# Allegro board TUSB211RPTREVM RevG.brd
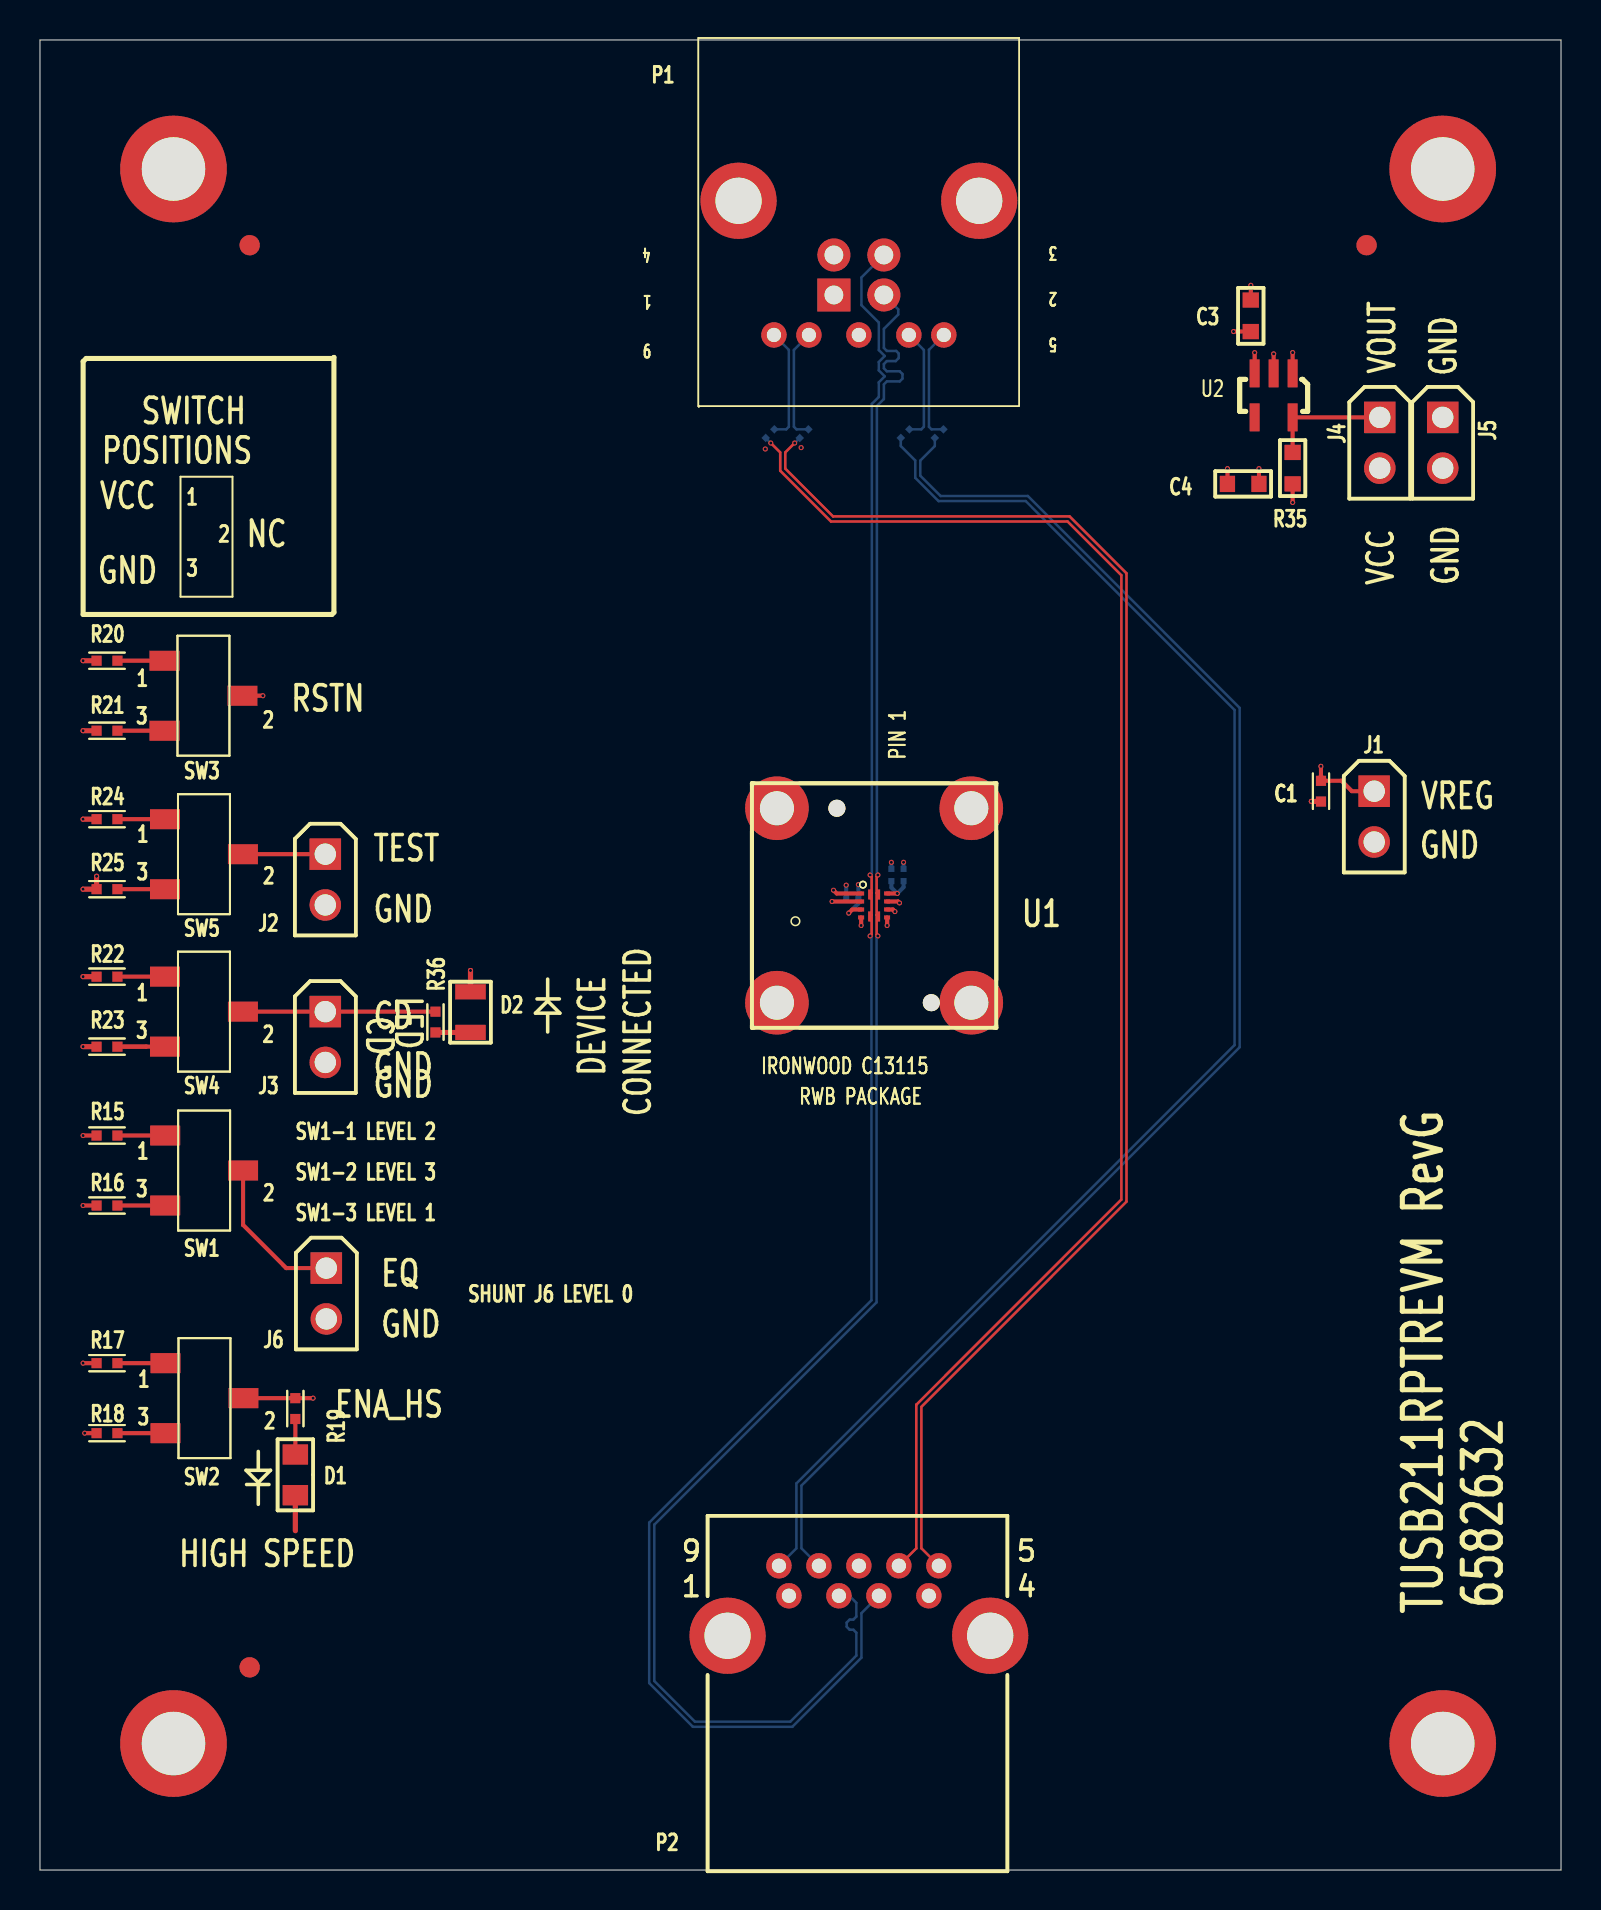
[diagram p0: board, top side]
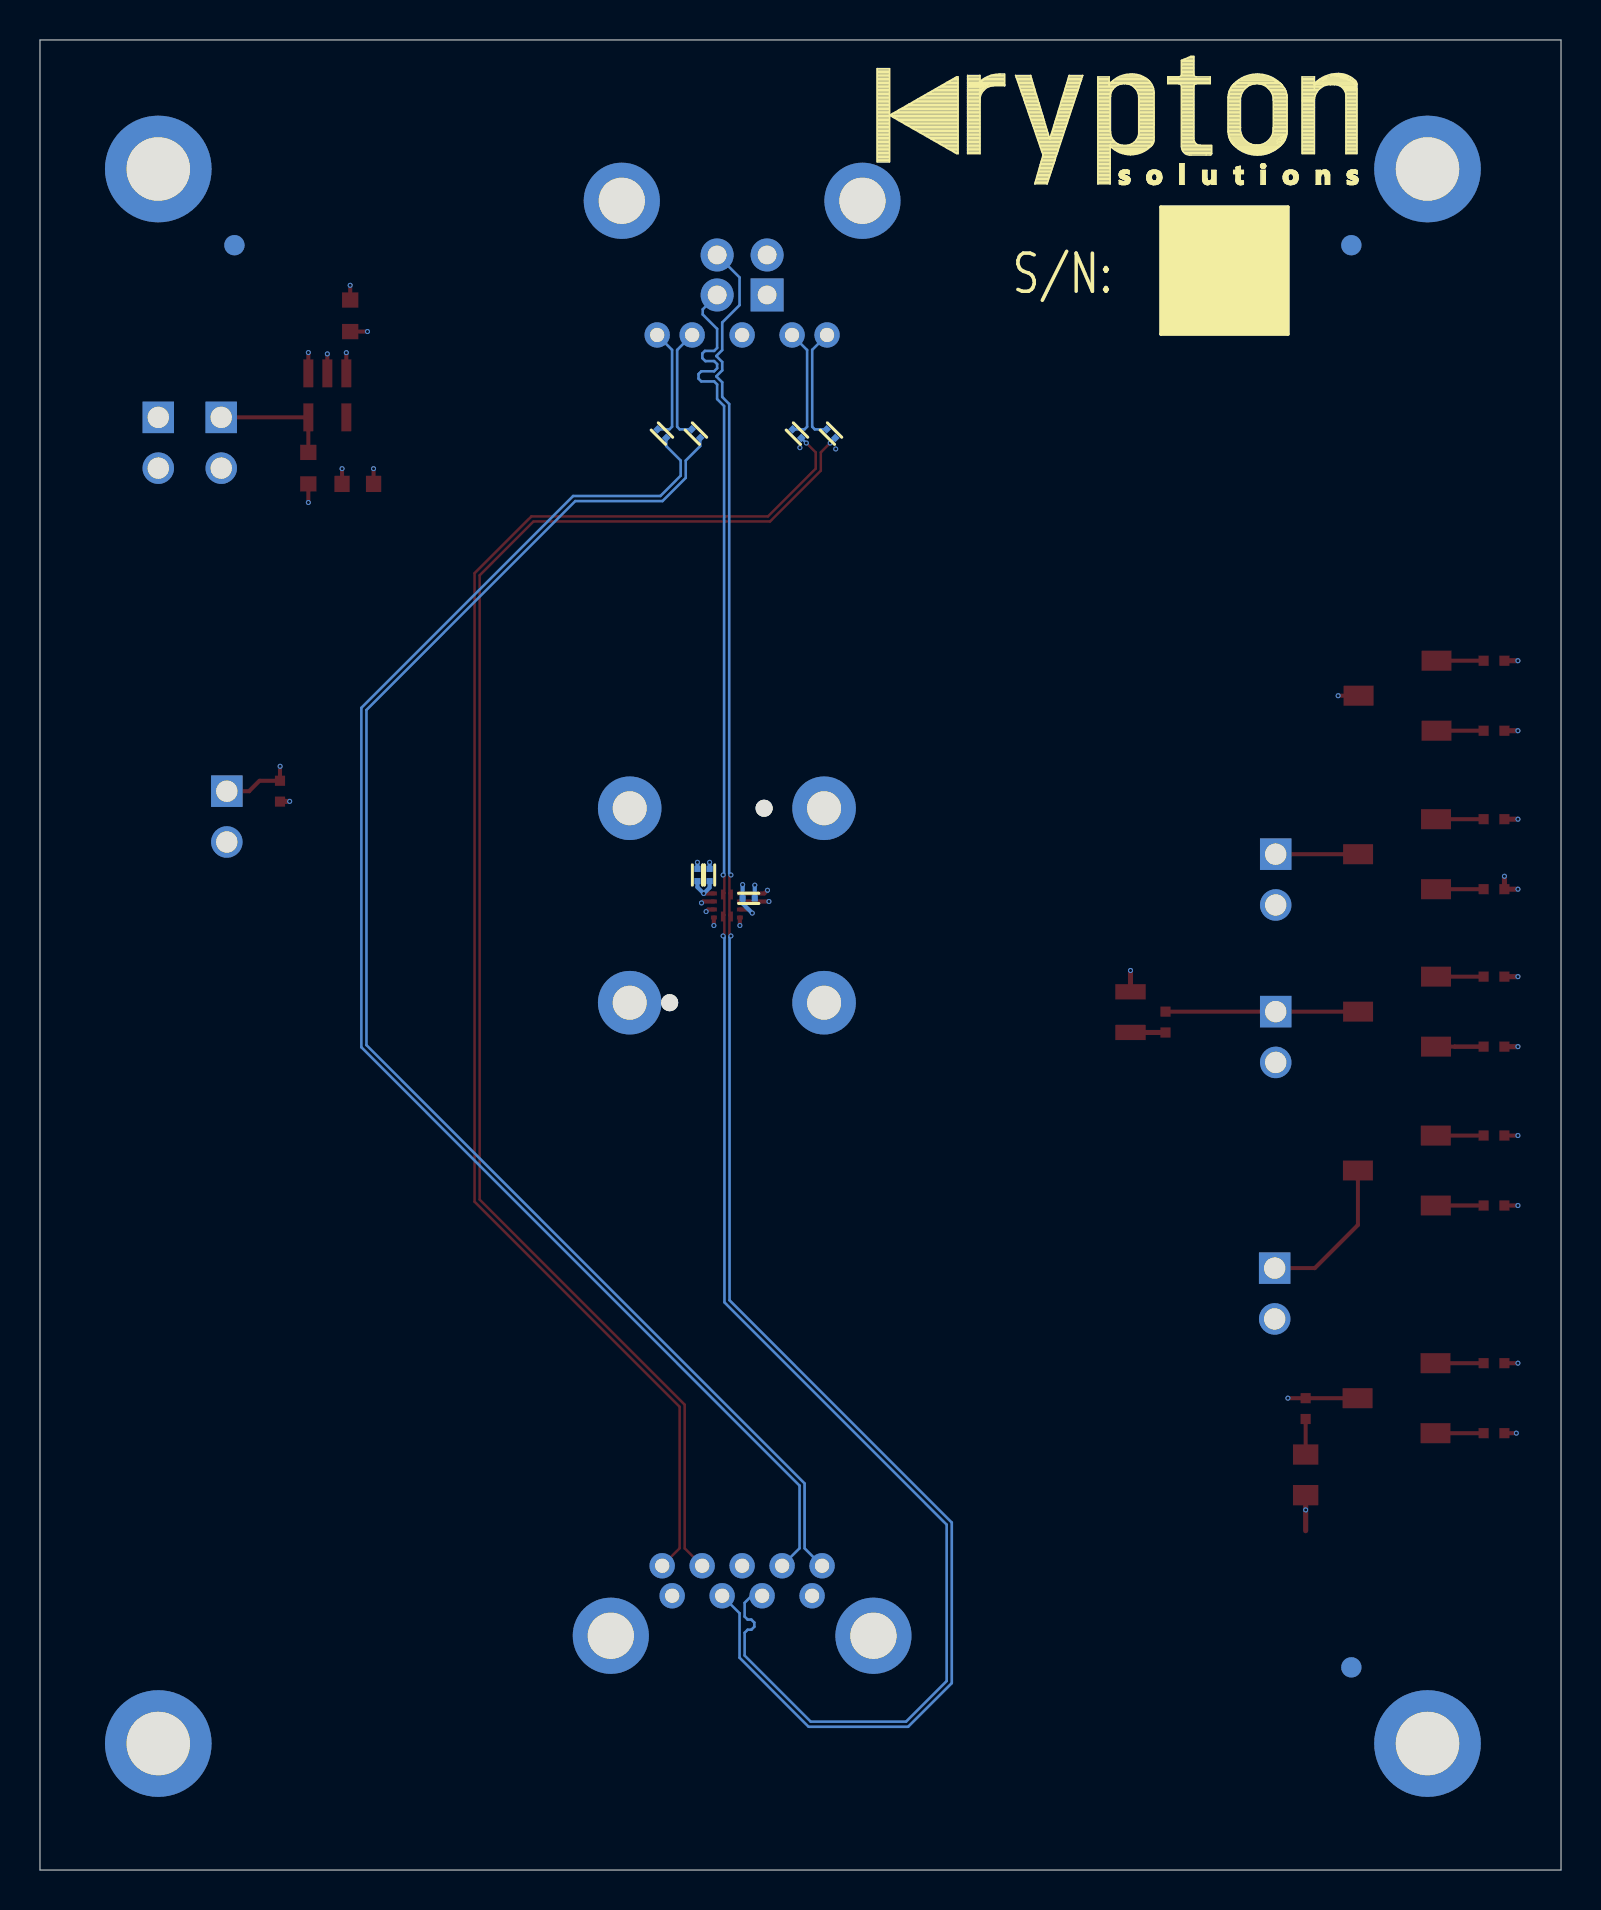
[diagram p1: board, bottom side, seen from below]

Outline 76.1 x 91.52 mm; copper layers: TOP, L2, L3, L4, L5, BOTTOM. Coordinates in mm from the lower left corner of the outline.
Outline path: 0,91.52 76.1,91.52 76.1,0 0,0 0,91.52

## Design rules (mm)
constraint set DEFAULT: min track width 0.127
net group DIFFPAIR4: nets SS_P2_RXN SS_P2_RXP
net group DIFFPAIR5: nets SS_P2_TXN SS_P2_TXP
net group DP1: nets N16594201 N16594205

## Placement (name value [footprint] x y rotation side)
C1  0.1uF  [0402]  64.09 53.95 270 top
C2  0.1uF  [0201]  40.64 48.59 180 bottom
C3  1uF  [0603]  60.58 77.72 90 top
C4  1uF  [0603]  60.2 69.32 180 top
C5  1uF  [0201]  42.6 49.76 90 bottom
C6  0.1uF  [0201]  43.21 49.76 90 bottom
D1  LED  [0805]  12.78 19.76 90 top
D2  LED  [CC0805]  21.54 43.92 270 top
J1  HDR2X1 M .1  [CON_THVT_1X2_100_M]  66.75 53.95 180 top
J2  HDR2X1 M .1  [CON_THVT_1X2_100_M]  14.27 50.8 180 top
J3  HDR2X1 M .1  [CON_THVT_1X2_100_M]  14.27 42.93 180 top
J4  HDR2X1 M .1  [CON_THVT_1X2_100_M]  67.03 72.64 180 top
J5  HDR2X1 M .1  [CON_THVT_1X2_100_M]  70.18 72.64 180 top
J6  HDR2X1 M .1  [CON_THVT_1X2_100_M]  14.33 30.1 180 top
M*  -  [unnamed]  6.68 85.06 0 top
M*#2  -  [unnamed]  70.18 6.32 0 top
M*#3  -  [unnamed]  70.18 85.06 0 top
M*#4  -  [unnamed]  6.68 6.32 0 top
NOREF  -  [#2]  847.93 330.56 0 top
NOREF#2  -  [#2]  76.1 0 90 top
NOREF#3  -  [unnamed]  10.49 10.13 0 top
NOREF#4  -  [#2]  -0.46 -18.57 0 top
NOREF#5  -  [#2]  96.6 85.95 0 top
NOREF#6  -  [unnamed]  10.49 81.25 0 top
NOREF#7  -  [unnamed]  66.37 81.25 0 top
NOREF#8  -  [#2]  66.95 3.91 90 top
NOREF#9  -  [#2]  0 91.52 0 top
NOREF#10  -  [unnamed]  66.37 81.25 180 bottom
NOREF#11  -  [unnamed]  10.49 81.25 180 bottom
NOREF#12  -  [#2]  22.2 8.08 180 bottom
NOREF#13  -  [#2]  27 79.98 180 bottom
NOREF#14  -  [#2]  34.26 84.25 180 bottom
NOREF#15  -  [unnamed]  10.49 10.13 180 bottom
P1  USB3_STANDARD_TYPE_B_RECEPTACLE  [USB3_TYPEB_AK4AA009]  39.72 78.77 180 top
P2  USB3_STANDARD_TYPE-A_RECEPTACLE  [USB3_TYPEA]  40.97 15.21 0 top
R3  0 Ohm  [0201]  44.98 71.83 225 bottom
R4  0 Ohm  [0201]  43.28 71.83 225 bottom
R5  0 Ohm  [0201]  38.23 71.83 225 bottom
R6  0 Ohm  [0201]  36.53 71.83 225 bottom
R15  4k Ohm  [0402]  3.35 36.73 0 top
R16  2k Ohm  [0402]  3.35 33.23 180 top
R17  4.7k  [0402]  3.35 25.35 0 top
R18  0 Ohm  [0402]  3.35 21.85 0 top
R19  75  [0402]  12.78 23.08 270 top
R20  4.7k  [0402]  3.35 60.47 0 top
R21  0 Ohm  [0402]  3.35 56.97 180 top
R22  4.7k  [0402]  3.35 44.68 0 top
R23  0 Ohm  [0402]  3.35 41.18 180 top
R24  4.7k  [0402]  3.35 52.55 0 top
R25  0 Ohm  [0402]  3.35 49.05 180 top
R35  0 Ohm  [0603]  62.67 70.1 270 top
R36  75  [0402]  19.79 42.41 270 top
SW1  Switch CJS-1201  [CJS-1200B]  8.21 34.98 0 top
SW2  Switch CJS-1201  [CJS-1200B]  8.23 23.6 0 top
SW3  Switch CJS-1201  [CJS-1200B]  8.18 58.72 0 top
SW4  Switch CJS-1201  [CJS-1200B]  8.2 42.93 0 top
SW5  Switch CJS-1201  [CJS-1200B]  8.2 50.8 0 top
U1  TUSB2x1RWB  [IRONWOOD_12PIN_C13115]  41.73 48.23 270 top
U2  LP5907  [DBV_R-PDSO-G5]  61.72 73.74 270 top

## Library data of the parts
C1 C2 C6 = cc0402
C3-C5 = cc0603
D1 = d0805 Green
D2 = d0805 Yellow
J1-J6 = HDR2X1 M .1
P1 = USB3_STANDARD_TYPE_B_RECEPTACLE
P2 = USB3_STANDARD_TYPE-A_RECEPTACLE
R3-R6 = r0201
R15-R25 R36 = r0402
R35 = r0603
SW1-SW5 = Switch CJS-1201
U1 = TUSB2x1RWB_0
U2 = LP5907

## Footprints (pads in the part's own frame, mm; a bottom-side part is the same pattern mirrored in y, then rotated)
0201
  rect 0.305x0.305 smd: 1(-0.305,0) 2(0.305,0)
0402
  rect 0.508x0.508 smd: 1(-0.521,0) 2(0.521,0)
0603
  rect 0.762x0.813 smd: 1(-0.787,0) 2(0.787,0)
0805
  rect 1.016x1.27 smd: 1(-1.016,0) 2(1.016,0)
CC0805
  rect 0.762x1.524 smd: 1(0,0) 2(2.032,0)
CJS-1200B
  rect 1.5x1 smd: 1(-1.95,1.75) 2(1.95,0) 3(-1.95,-1.75)
CON_THVT_1X2_100_M
  rect 1.575x1.575 hole 1.067: 1(0,0)
  round 1.575 hole 1.067: 2(0,2.54)
DBV_R-PDSO-G5
  rect 1.4x0.5 smd: 1(-1.1,0.95) 2(-1.1,0) 3(-1.1,-0.95) 4(1.1,-0.95) 5(1.1,0.95)
IRONWOOD_12PIN_C13115
  round 3.18 hole 1.7: (-4.862,4.862) (-4.862,-4.862) (4.862,4.862) (4.862,-4.862)
  round 0.85 hole 0.85 unplated: (-4.862,-1.862) (4.862,2.862)
  rect 0.5x0.2 smd: 1(-0.55,0.2) 2(-0.55,-0.2) 7(0.55,-0.2) 8(0.55,0.2)
  rect 0.2x0.3 smd: 3(-0.6,-0.65) 4(-0.2,-0.65) 5(0.2,-0.65) 6(0.6,-0.65) 9(0.6,0.65) 10(0.2,0.65) 11(-0.2,0.65) 12(-0.6,0.65)
unnamed
  round 5.334 hole 3.175: (0,0)
USB3_TYPEA
  round 1.27 hole 0.711: 1(-3.5,-1.5) 2(-1,-1.5) 3(1,-1.5) 4(3.5,-1.5) 5(4,0) 6(2,0) 7(0,0) 8(-2,0) 9(-4,0)
  round 3.81 hole 2.311: 10(-6.57,-3.5) 11(6.57,-3.5)
USB3_TYPEB_AK4AA009
  rect 1.651x1.651 hole 0.94: 1(0,0)
  round 1.651 hole 0.94: 2(-2.5,0) 3(-2.5,-2) 4(0,-2)
  round 1.27 hole 0.711: 5(-5.5,2) 6(-3.75,2) 7(-1.25,2) 8(1.25,2) 9(3,2)
  round 3.81 hole 2.311: 10(-7.27,-4.71) 11(4.77,-4.71)

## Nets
GND: C1.2 C2.2 C3.2 C4.2 C5.2 C6.2 D1.1 D2.1 J1.2 J2.2 J3.2 J5.1 J5.2 J6.2 P1.4 P1.7 P1.10 P1.11 P2.4 P2.7 P2.10 P2.11 R15.1 R16.2 R18.1 R21.2 R23.2 R25.2 U1.10 U2.2
VBUS: C3.1 P1.1(VBUS_PWR) P2.1(VBUS_PWR) U2.1 U2.3
VCC: C4.1 C5.1 C6.1 J4.2 R17.1 R20.1 R22.1 R24.1 R35.2 U1.12
CD: J3.1 R36.1 SW4.2 U1.4
ENA_HS: R19.1 SW2.2 U1.9
EQ: J6.1 SW1.2 U1.6
RSTN: C2.1 SW3.2 U1.5
SS_P2_RXN: P2.5 R5.2
SS_P2_RXP: P2.6 R6.2
SS_P2_TXN: P2.8 R3.2
SS_P2_TXP: P2.9 R4.2
TEST: J2.1 SW5.2 U1.3
N16594201: P1.3 P2.3 U1.2 U1.7
N16594205: P1.2 P2.2 U1.1 U1.8
N16594567: P1.5 R3.1
N16594571: P1.6 R4.1
N16594575: P1.8 R5.1
N16594579: P1.9 R6.1
N16603335: R15.2 SW1.1
N16603355: R16.1 SW1.3
N16603371: R17.2 SW2.1
N16603379: R18.2 SW2.3
N16603391: R20.2 SW3.1
N16603403: R21.1 SW3.3
N16603419: R22.2 SW4.1
N16603427: R23.1 SW4.3
N16603439: R24.2 SW5.1
N16603451: R25.1 SW5.3
N16603507: D1.2 R19.2
N16603717: C1.1 J1.1 U1.11(VREG)
N16608838: J4.1 R35.1 U2.5(VOUT)
N16618316: D2.2 R36.2

Pads without a net: U2 4

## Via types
v1: diameter 0.254, hole 0.152, TOP to BOTTOM, 45 vias

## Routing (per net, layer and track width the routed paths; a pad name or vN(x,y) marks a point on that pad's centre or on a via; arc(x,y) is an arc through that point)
GND: length 220
  TOP w0.203: C3.2 v1(60.58,79.25) ; U1.10 42.67,48.03 v1(42.77,47.93) ; R18.1 v1(2.24,21.85) ; C4.2 v1(59.41,70.08) ; R16.2 v1(2.16,33.23) ; R15.1 v1(2.16,36.73) ; U2.2 v1(61.72,75.82)
  TOP w0.254: v1(2.83,49.7) R25.2 v1(2.16,49.05) ; 12.78,16.97 v1(12.78,18.01) D1.1 ; C1.2 v1(63.61,53.44) ; R21.2 v1(2.16,56.97) ; D2.1 v1(21.54,44.98) ; R23.2 v1(2.16,41.18)
  L2 w0.127: P2.11 49.62,11.71 ; P2.11 45.46,11.71 ; P2.11 47.54,9.63 ; P2.11 47.54,13.8 ; 34.95,81.39 P1.11 ; P1.11 32.87,83.48 ; P1.11 37.03,83.48 ; P1.11 34.95,85.56 ; 32.32,11.71 P2.10 ; P2.10 34.4,13.8 ; P2.10 34.4,9.63 ; P2.10 36.48,11.71 ; P1.10 46.99,85.56 ; P1.10 49.07,83.48 ; P1.10 44.91,83.48 ; P1.10 46.99,81.39 ; P1.7 41.78,76.77 ; P1.7 40.97,75.95 ; P1.7 40.97,77.58 ; P1.7 40.16,76.77 ; P2.4 45.28,13.71 ; P2.4 44.47,14.53 ; P2.4 44.47,12.9 ; P2.4 43.66,13.71 ; P2.7 41.78,15.21 ; P2.7 40.97,14.4 ; P2.7 40.97,16.03 ; P2.7 40.16,15.21 ; P1.4 39.72,81.77 ; P1.4 38.72,80.77 ; P1.4 40.72,80.77
  L2 w0.635: J5.2 70.18,71.07 ; J5.2 70.18,69.14 ; J5.2 69.21,70.1 ; J5.2 71.15,70.1 ; 14.33,26.59 J6.2 ; J6.2 14.33,28.52 ; J6.2 13.36,27.56 ; J6.2 15.29,27.56 ; J3.2 15.24,40.39 ; J3.2 14.27,39.42 ; J3.2 14.27,41.35 ; J3.2 13.31,40.39 ; 69.21,72.64 J5.1 ; J5.1 70.18,73.61 ; J5.1 71.15,72.64 ; J5.1 70.18,71.68 ; J1.2 67.72,51.41 ; J1.2 66.75,52.38 ; J1.2 66.75,50.44 ; J1.2 65.79,51.41 ; J2.2 15.24,48.26 ; J2.2 13.31,48.26 ; J2.2 14.27,49.23 ; J2.2 14.27,47.29
  L4 w0.127: 34.95,81.39 P1.11 ; P1.11 34.95,85.56 ; P1.11 37.03,83.48 ; P1.11 32.87,83.48 ; P1.4 39.72,81.77 ; P1.4 40.72,80.77 ; P1.4 38.72,80.77 ; 40.16,76.77 P1.7 ; P1.7 41.78,76.77 ; P1.7 40.97,75.95 ; P1.7 40.97,77.58 ; 45.46,11.71 P2.11 ; P2.11 47.54,9.63 ; P2.11 47.54,13.8 ; P2.11 49.62,11.71 ; 40.97,14.4 P2.7 ; P2.7 40.97,16.03 ; P2.7 40.16,15.21 ; P2.7 41.78,15.21 ; P1.10 46.99,85.56 ; P1.10 44.91,83.48 ; P1.10 46.99,81.39 ; P1.10 49.07,83.48 ; 44.47,12.9 P2.4 ; P2.4 45.28,13.71 ; P2.4 44.47,14.53 ; P2.4 43.66,13.71 ; 32.32,11.71 P2.10 ; P2.10 34.4,9.63 ; P2.10 36.48,11.71 ; P2.10 34.4,13.8
  L4 w0.635: 70.18,69.14 J5.2 ; J5.2 70.18,71.07 ; J5.2 69.21,70.1 ; J5.2 71.15,70.1 ; J6.2 15.29,27.56 ; J6.2 14.33,26.59 ; J6.2 14.33,28.52 ; J6.2 13.36,27.56 ; 14.27,47.29 J2.2 ; J2.2 14.27,49.23 ; J2.2 15.24,48.26 ; J2.2 13.31,48.26 ; 14.27,39.42 J3.2 ; J3.2 13.31,40.39 ; J3.2 15.24,40.39 ; J3.2 14.27,41.35 ; J5.1 70.18,73.61 ; J5.1 70.18,71.68 ; J5.1 69.21,72.64 ; J5.1 71.15,72.64 ; J1.2 66.75,52.38 ; J1.2 65.79,51.41 ; J1.2 66.75,50.44 ; J1.2 67.72,51.41
  L5 w0.127: P2.10 34.4,13.8 ; P2.10 32.32,11.71 ; P2.10 34.4,9.63 ; P2.10 36.48,11.71 ; P2.11 47.54,13.8 ; P2.11 45.46,11.71 ; P2.11 49.62,11.71 ; P2.11 47.54,9.63 ; 40.97,14.4 P2.7 ; P2.7 40.97,16.03 ; P2.7 40.16,15.21 ; P2.7 41.78,15.21 ; P1.4 40.72,80.77 ; P1.4 39.72,81.77 ; P1.4 38.72,80.77 ; 46.99,81.39 P1.10 ; P1.10 44.91,83.48 ; P1.10 49.07,83.48 ; P1.10 46.99,85.56 ; P2.4 45.28,13.71 ; P2.4 43.66,13.71 ; P2.4 44.47,14.53 ; P2.4 44.47,12.9 ; P1.11 37.03,83.48 ; P1.11 34.95,81.39 ; P1.11 32.87,83.48 ; P1.11 34.95,85.56 ; 40.97,75.95 P1.7 ; P1.7 40.16,76.77 ; P1.7 40.97,77.58 ; P1.7 41.78,76.77
  L5 w0.635: 69.21,72.64 J5.1 ; J5.1 70.18,73.61 ; J5.1 70.18,71.68 ; J5.1 71.15,72.64 ; 13.31,48.26 J2.2 ; J2.2 15.24,48.26 ; J2.2 14.27,49.23 ; J2.2 14.27,47.29 ; J6.2 15.29,27.56 ; J6.2 14.33,26.59 ; J6.2 13.36,27.56 ; J6.2 14.33,28.52 ; 69.21,70.1 J5.2 ; J5.2 71.15,70.1 ; J5.2 70.18,69.14 ; J5.2 70.18,71.07 ; J1.2 67.72,51.41 ; J1.2 66.75,50.44 ; J1.2 66.75,52.38 ; J1.2 65.79,51.41 ; J3.2 14.27,41.35 ; J3.2 14.27,39.42 ; J3.2 13.31,40.39 ; J3.2 15.24,40.39
  BOTTOM w0.203: C5.2 v1(42.6,50.39) ; C6.2 v1(43.21,50.39) ; C2.2 v1(40.34,49.25)
  vias: v1(36.29,71.06) v1(38.08,71.13)
VBUS: length 9.2
  TOP w0.203: C3.1 v1(59.72,76.94) ; U2.3 v1(60.77,75.88) ; v1(62.67,75.89) U2.1
  L3 w0.127: P2.1 37.47,14.53 ; P2.1 36.66,13.71 ; P2.1 38.28,13.71 ; P2.1 37.47,12.9 ; 39.72,77.76 P1.1 ; P1.1 40.72,78.77 ; P1.1 38.72,78.77
VCC: length 10.3
  TOP w0.203: R17.1 v1(2.16,25.35) ; U1.12 v1(42.89,48.83) ; C4.1 v1(60.99,70.08) ; R35.2 v1(62.67,68.39)
  TOP w0.254: R24.1 v1(2.16,52.55) ; R22.1 v1(2.16,44.68) ; R20.1 v1(2.16,60.47)
  L3 w0.635: 67.03,69.14 J4.2 ; J4.2 68,70.1 ; J4.2 66.06,70.1 ; J4.2 67.03,71.07
  BOTTOM w0.203: C6.1 43.21,49.15 v1(42.89,48.83) 42.6,49.13 C5.1
CD: length 38.7
  TOP w0.203: SW4.2 J3.1 R36.1 ; U1.4 v1(39.63,48.43)
  L4 w0.203: J3.1 26.31,42.93 31.82,48.43 v1(39.63,48.43)
ENA_HS: length 46.4
  TOP w0.203: SW2.2 R19.1 v1(13.67,23.6) ; U1.9 v1(42.38,47.23)
  L4 w0.203: v1(42.38,47.23) 42.38,40.38 25.6,23.6 v1(13.67,23.6)
EQ: length 45.8
  TOP w0.203: J6.1 12.32,30.1 10.16,32.26 SW1.2 ; U1.6 v1(41.08,47.23)
  L4 w0.203: v1(41.08,47.23) 41.08,40.83 30.35,30.1 J6.1
RSTN: length 37.3
  TOP w0.203: U1.5 40.64,48.03 v1(40.46,47.85) ; SW3.2 v1(11.15,58.72)
  L4 w0.203: v1(40.94,49.28) 40.94,49.63 39.97,50.61 31.56,50.61 23.44,58.72 v1(11.15,58.72)
  BOTTOM w0.203: v1(40.46,47.85) 40.94,48.34 C2.1 v1(40.94,49.28)
SS_P2_RXN: length 75.3
  TOP w0.127: v1(37.76,71.36) 37.29,70.89 37.29,70.08 39.68,67.69 51.52,67.69 54.36,64.85 54.36,33.42 44.1,23.16 44.1,16.09 P2.5
  BOTTOM w0.127: R5.2 v1(37.76,71.36)
SS_P2_RXP: length 75.3
  TOP w0.127: P2.6 43.84,16.09 43.84,23.27 54.1,33.53 54.1,64.74 51.41,67.44 39.57,67.44 37.03,69.98 37.03,70.89 v1(36.56,71.36)
  BOTTOM w0.127: R6.2 v1(36.56,71.36)
SS_P2_TXN: length 75.3
  BOTTOM w0.127: P2.8 38.1,16.09 38.1,19.23 60.02,41.15 60.02,58.12 49.42,68.71 45.06,68.71 44.04,69.73 44.04,70.48 44.77,71.21 R3.2
SS_P2_TXP: length 75.3
  BOTTOM w0.127: P2.9 37.84,16.09 37.84,19.33 59.77,41.25 59.77,58.01 49.32,68.46 44.95,68.46 43.79,69.62 43.79,70.49 43.07,71.21 R4.2
TEST: length 31.7
  TOP w0.203: U1.3 39.86,48.83 v1(39.7,49) ; J2.1 SW5.2
  L4 w0.203: J2.1 29.72,50.8 30.99,49.53 39.17,49.53 v1(39.7,49)
N16594201: length 94.2
  TOP w0.127: 41.61,47.76 41.61,48.86 ; 41.61,47.76 U1.7 ; 41.61,47.76 41.61,46.78 v1(41.53,46.71) ; 41.61,48.86 41.61,49.68 v1(41.53,49.76) ; 41.61,48.86 U1.2
  BOTTOM w0.127: v1(41.53,46.71) 41.6,46.64 41.6,28.49 30.48,17.37 30.48,9.35 32.66,7.16 37.64,7.16 41.1,10.62 41.1,12.84 P2.3 ; P1.3 41.1,79.64 41.1,78.26 41.97,77.39 41.97,76.01 42.26,75.71 41.97,75.41 41.97,74.99 42.26,74.7 41.97,74.4 41.97,73.67 41.62,73.32 41.62,49.85 v1(41.53,49.76)
N16594205: length 94.2
  TOP w0.127: v1(41.92,46.71) 41.86,46.77 41.86,47.76 ; 41.86,47.76 41.86,48.86 ; 41.86,47.76 U1.8 ; 41.86,48.86 U1.1 ; 41.86,48.86 41.86,49.7 v1(41.92,49.76)
  BOTTOM w0.127: P1.2 42.94,78.05 42.94,77.79 42.22,77.07 42.22,76.12 42.37,75.97 42.83,75.97 42.96,75.84 42.96,75.61 42.81,75.46 42.37,75.46 42.22,75.31 42.22,75.1 42.37,74.95 43.01,74.95 43.15,74.81 43.15,74.58 43.01,74.44 42.37,74.44 42.22,74.29 42.22,73.56 41.87,73.21 41.87,49.81 v1(41.92,49.76) ; v1(41.92,46.71) 41.85,46.64 41.85,28.39 30.73,17.27 30.73,9.45 32.77,7.42 37.54,7.42 40.84,10.72 40.84,11.87 40.69,12.02 40.51,12.02 40.36,12.16 40.36,12.37 40.51,12.52 40.69,12.52 40.84,12.67 40.84,13.36 40.49,13.71 P2.2
N16594567: length 5.7
  BOTTOM w0.127: P1.5 44.48,76.02 44.48,72.17 44.6,72.05 45.2,72.05
N16594571: length 5.7
  BOTTOM w0.127: P1.6 44.22,76.01 44.22,72.17 44.09,72.05 R4.1
N16594575: length 5.7
  BOTTOM w0.127: P1.8 37.72,76.01 37.72,72.17 37.85,72.05 R5.1
N16594579: length 5.7
  BOTTOM w0.127: P1.9 37.46,76.02 37.46,72.17 37.34,72.05 R6.1
N16603335: length 2.4
  TOP w0.203: SW1.1 R15.2
N16603355: length 2.4
  TOP w0.203: SW1.3 R16.1
N16603371: length 2.4
  TOP w0.203: SW2.1 R17.2
N16603379: length 2.4
  TOP w0.203: SW2.3 R18.2
N16603391: length 2.4
  TOP w0.203: SW3.1 R20.2
N16603403: length 2.4
  TOP w0.203: SW3.3 R21.1
N16603419: length 2.4
  TOP w0.203: SW4.1 R22.2
N16603427: length 3.8
  TOP w0.203: SW4.3 5.31,41.18 ; 5.31,41.18 R23.1 ; 5.31,41.18 5.31,41.17 3.9,41.17
N16603439: length 2.4
  TOP w0.203: SW5.1 R24.2
N16603451: length 2.4
  TOP w0.203: SW5.3 R25.1
N16603507: length 1.8
  TOP w0.203: R19.2 D1.2
N16603717: length 28.2
  TOP w0.203: J1.1 65.63,53.95 65.11,54.47 C1.1 64.09,55.19 v1(64.08,55.19) ; U1.11 42.93,48.43 v1(43,48.36)
  L4 w0.508: v1(43,48.36) 57.25,48.36 v1(64.08,55.19)
N16608838: length 6.1
  TOP w0.203: J4.1 U2.5 R35.1
N16618316: length 1.8
  TOP w0.254: R36.2 D2.2

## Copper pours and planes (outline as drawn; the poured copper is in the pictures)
GND on L2, L5: 0.51,0.51 75.59,0.51 75.59,91.01 0.51,91.01
GND on L4: 0.51,0.51 0.51,91.01 75.59,91.01 75.59,0.51 ; 1 cut-out
VBUS on L3: 0.51,0.51 0.51,14.83 68.97,14.83 70.48,16.35 70.48,72.83 70.11,73.2 32.08,73.2 32.08,91.01 75.59,91.01 75.59,0.51
VCC on L3: 0.51,15.85 0.51,91.01 31.06,91.01 31.06,72.19 69.47,72.19 69.47,16.77 68.55,15.85

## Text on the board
BOTTOM: LAYER - BOTTOM
Board Geometry/Soldermask Bottom: LAYER - SOLDERMASK BOTTOM
Package Geometry/Pastemask Bottom: LAYER - PASTEMASK BOTTOM
Ref Des/Silkscreen Bottom: LAYER - SILK BOTTOM
User.Comments: GENERAL NOTES. UNLESS OTHERWISE SPECIFIED | 1.  ALL FABRICATION ITEMS MUST MEET OR EXCEED BEST | INDUSTRY PRACTICE : IPC-A-600C (Commercial std.) | 2.  LAMINATE MATERIAL  :  FR4 POLYCLAD 370 or EQUIVALENT | 3.  COPPER WEIGHT  : 1oz START INTERNAL, 1/2oz START EXTERNAL | 4.  FINISHED BOARD THICKNESS :  .062  +/- 10% | 5.  MAXIMUM WARP AND TWIST TO BE :  .005 INCH PER INCH | 6.  MINIMUM COPPER WALL THICKNESS OF PLATED-THRU | HOLES TO BE .001 INCH. THERE MUST BE 1MIL OR GREATER PLATING ON | EACH SIDE OF THE BARREL WHEN VIEWED IN THE CROSS SECTION | 7.  MINIMUM ANNULAR RING OF PLATED-THRU HOLES | TO BE .002 INCH | 8.  MAXIMUM ALLOWABLE LINE REDUCTION TO BE | 20% OR .002 WHICHEVER IS SMALLER | 9.  0.005 SIGNAL LINES ON LAYER 1 & 6 TO BE | IMPEDANCE CONTROLLED 100 OHMS DIFFERENTIAL +/- 10% | 10. 0.008 SIGNAL LINES ON LAYER 1 & 6 TO BE | IMPEDANCE CONTROLLED 50 OHMS +/- 10% | 11. TRACE WIDTH CALCULATIONS ARE STARTING VALUES. BOARD SHOP MAY ADJUST | TRACE WIDTHS TO COMPENSATE FOR PROCESS. | 12. DIELECTRIC CONSTANTS ARE         CORE : 4.1 | PREPREG : 4.1 | 14. A CROSS SECTION MOUNT AND DIGITAL PHOTO'S OF VIA'S TO BE PROVIDED | 15. THIEVING IS ALLOWED | PROCESS NOTES | 1. CIRCUITRY ON OUTER LAYERS TO BE PLATED WITH : ENIG | 3. SOLDERMASK BOTH SIDES PER ARTWORK  :  GREEN LPI | 4. SILKSCREEN BOTH SIDES PER ARTWORK  :  COLOR = WHITE
TOP: LAYER - TOP
Board Geometry/Soldermask Top: LAYER - SOLDERNASK TOP
Package Geometry/Pastemask Top: LAYER - PASTEMASK TOP
Ref Des/Silkscreen Top: 3 | 1 | 2 | SW1-1 LEVEL 2 | SW1-2 LEVEL 3 | SW1-3 LEVEL 1 | SHUNT J6 LEVEL 0 | GND | VCC | POSITIONS | SWITCH | HIGH SPEED | NC | RSTN | ENA_HS | TEST | CD | EQ | U1 | VREG | DEVICE | CONNECTED | VOUT | LAYER - SILK TOP | TUSB211RPTREVM RevG | 6582632
L2: LAYER - L2
L3: LAYER - L3
L4: LAYER - L4
L5: LAYER - L5
PAGE_OUTLINE: LAYER - FAB
User.13: FIGURE | SIZE | 6.0 | 28.0 | 37.0 | 42.0 | 66.93 | 91.0 | 125.0 | 33.46 | DRILL CHART: TOP to BOTTOM | ALL UNITS ARE IN MILS | TOLERANCE | +3.0/-3.0 | +2.0/-2.0 | PLATED | NON-PLATED | QTY | 45 | 14 | 4 | 12 | 2
